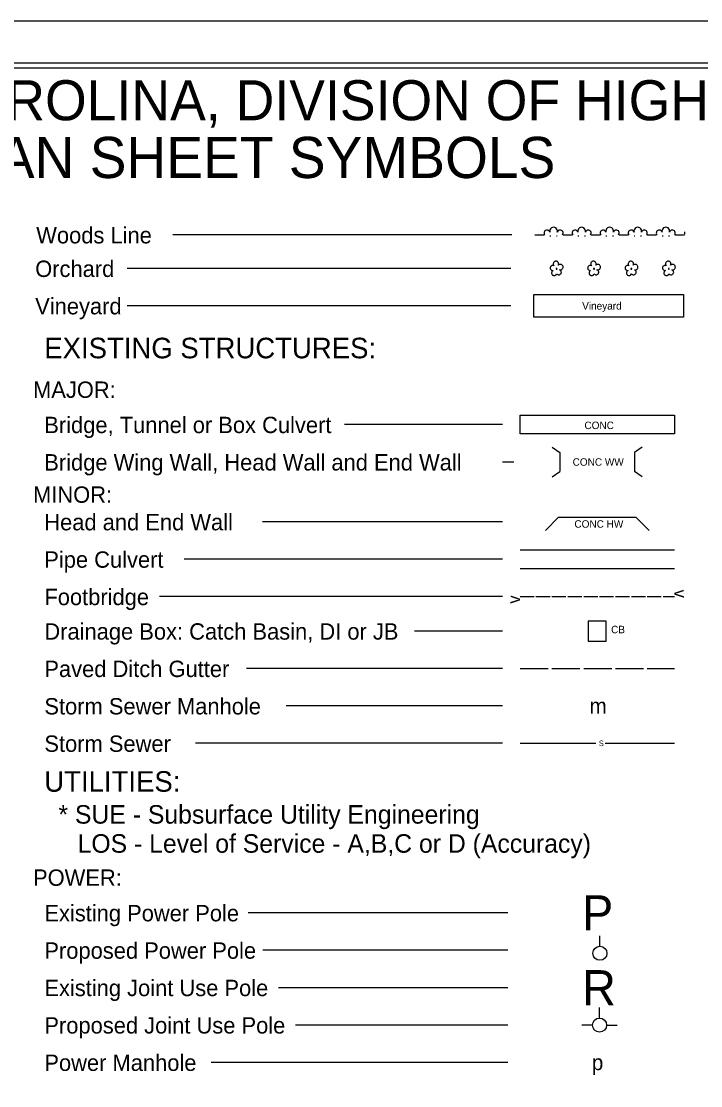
# Model space of a CAD drawing. Extents: x 147589369 to 147592737, y 91898723 to 91900923.
# Drawn here: x 147591216 to 147591942, y 91899785 to 91900923 of the extents above; entities that cross this region are included whole.
import ezdxf

# ---------------------------------------------------------------- set-up
doc = ezdxf.new("R2010")
doc.units = 0
for name, color, linetype in [('Sheet Cutting Line CELL', 7, 'Continuous'), ('Sheet Plot Border Inside CELL', 7, 'Continuous'), ('Sheet Plot Border Outside CELL', 7, 'Continuous'), ('Sheet Symbology CELL', 7, 'Continuous')]:
    doc.layers.add(name, color=color, linetype=linetype)

msp = doc.modelspace()

# ---------------------------------------------------------------- linework, layer by layer
at = {"layer": 'Sheet Cutting Line CELL'}
msp.add_line((147592737.3, 91900923.1), (147589369.3, 91900923.1), dxfattribs=at)
at = {"layer": 'Sheet Plot Border Inside CELL'}
msp.add_lwpolyline([(147589395.3, 91898768), (147592728.3, 91898768), (147592728.3, 91900878.2), (147589395.3, 91900878.2)], close=True, dxfattribs=at)
at = {"layer": 'Sheet Plot Border Outside CELL'}
msp.add_lwpolyline([(147589369.3, 91898723.1), (147592737.3, 91898723.1), (147592737.3, 91900923.1), (147589369.3, 91900923.1)], close=True, dxfattribs=at)
at = {"layer": 'Sheet Symbology CELL'}
for p, q in [((147591739.8, 91900694.5), (147591377.6, 91900694.5)), ((147591764.6, 91900694.5), (147591774.6, 91900694.5)), ((147591780.5, 91900693.5), (147591781.5, 91900693.5)), ((147591787.5, 91900693.5), (147591788.5, 91900693.5)), ((147591794.6, 91900694.5), (147591804.6, 91900694.5)), ((147591810.5, 91900693.5), (147591811.5, 91900693.5)), ((147591817.5, 91900693.5), (147591818.5, 91900693.5)), ((147591824.6, 91900694.5), (147591834.6, 91900694.5)), ((147591840.5, 91900693.5), (147591841.5, 91900693.5)), ((147591847.5, 91900693.5), (147591848.5, 91900693.5)), ((147591854.6, 91900694.5), (147591864.6, 91900694.5)), ((147591870.5, 91900693.5), (147591871.5, 91900693.5)), ((147591877.5, 91900693.5), (147591878.5, 91900693.5)), ((147591884.6, 91900694.5), (147591894.6, 91900694.5)), ((147591900.5, 91900693.5), (147591901.5, 91900693.5)), ((147591907.5, 91900693.5), (147591908.5, 91900693.5)), ((147591914.6, 91900694.5), (147591924.6, 91900694.5)), ((147591738.7, 91900658.7), (147591328.8, 91900658.7)), ((147591738.7, 91900618.7), (147591328.8, 91900618.7)), ((147591730.1, 91900491.7), (147591561.2, 91900491.7)), ((147591783, 91900467.4), (147591791.2, 91900461.7)), ((147591879.4, 91900467.4), (147591871.2, 91900461.7)), ((147591730.1, 91900451.7), (147591742, 91900451.7)), ((147591791.2, 91900461.7), (147591791.2, 91900441.7)), ((147591871.2, 91900461.7), (147591871.2, 91900441.7)), ((147591783, 91900435.9), (147591791.2, 91900441.7)), ((147591879.4, 91900435.9), (147591871.2, 91900441.7)), ((147591730.1, 91900387.7), (147591473.5, 91900387.7)), ((147591775.8, 91900378.5), (147591789.9, 91900392.7)), ((147591789.9, 91900392.7), (147591872.4, 91900392.7)), ((147591872.4, 91900392.7), (147591886.6, 91900378.5)), ((147591748.7, 91900357.7), (147591913.7, 91900357.7)), ((147591730.1, 91900347.7), (147591389.7, 91900347.7)), ((147591748.7, 91900337.7), (147591913.7, 91900337.7)), ((147591730.1, 91900307.7), (147591363.1, 91900307.7)), ((147591748.7, 91900307.7), (147591763.7, 91900307.7)), ((147591765.7, 91900307.7), (147591780.7, 91900307.7)), ((147591782.7, 91900307.7), (147591797.7, 91900307.7)), ((147591799.7, 91900307.7), (147591814.7, 91900307.7)), ((147591816.7, 91900307.7), (147591831.7, 91900307.7)), ((147591833.7, 91900307.7), (147591848.7, 91900307.7)), ((147591850.7, 91900307.7), (147591865.7, 91900307.7)), ((147591867.7, 91900307.7), (147591882.7, 91900307.7)), ((147591884.7, 91900307.7), (147591899.7, 91900307.7)), ((147591901.7, 91900307.7), (147591913.7, 91900307.7)), ((147591730.1, 91900270.8), (147591635.7, 91900270.8)), ((147591730.1, 91900230.8), (147591456.2, 91900230.8)), ((147591748.7, 91900230.8), (147591778.7, 91900230.8)), ((147591782.7, 91900230.8), (147591812.7, 91900230.8)), ((147591816.7, 91900230.8), (147591846.7, 91900230.8)), ((147591850.7, 91900230.8), (147591880.7, 91900230.8)), ((147591884.7, 91900230.8), (147591913.7, 91900230.8)), ((147591730.1, 91900190.8), (147591498.7, 91900190.8)), ((147591730.1, 91900150.8), (147591401.7, 91900150.8)), ((147591748.7, 91900150.8), (147591829.7, 91900150.8)), ((147591839.7, 91900150.8), (147591913.7, 91900150.8)), ((147591735.6, 91899969.4), (147591458.2, 91899969.4)), ((147591834.1, 91899933.7), (147591834.1, 91899944.9)), ((147591735.6, 91899929.4), (147591473.8, 91899929.4)), ((147591735.6, 91899889.4), (147591490.6, 91899889.4)), ((147591833.7, 91899857), (147591833.7, 91899868.2)), ((147591735.6, 91899849.4), (147591508.6, 91899849.4)), ((147591826.2, 91899849.5), (147591814.9, 91899849.5)), ((147591841.2, 91899849.5), (147591852.4, 91899849.5)), ((147591735.6, 91899809.4), (147591418.6, 91899809.4))]:
    msp.add_line(p, q, dxfattribs=at)
for points in [[(147592703.3, 91900873.1), (147589703.3, 91900873.1), (147589703.3, 91898775.1), (147592703.3, 91898775.1)], [(147591821.5, 91900260.2), (147591840.8, 91900260.2), (147591840.8, 91900281.5), (147591821.5, 91900281.5)]]:
    msp.add_lwpolyline(points, close=True, dxfattribs=at)
for points in [[(147591789.6, 91900662.2), (147591789.9, 91900662.8), (147591790, 91900663.4), (147591789.9, 91900664), (147591789.8, 91900664.6), (147591789.5, 91900665.1), (147591789.2, 91900665.6), (147591788.7, 91900666), (147591788.2, 91900666.3), (147591787.5, 91900666.5), (147591787, 91900666.5), (147591786.4, 91900666.4), (147591785.8, 91900666.2), (147591785.3, 91900665.9), (147591784.8, 91900665.5), (147591784.5, 91900664.9), (147591784.3, 91900664.4), (147591784.2, 91900663.8), (147591784.2, 91900663.2), (147591784.3, 91900662.6), (147591784.6, 91900662.1), (147591785, 91900661.5), (147591784.5, 91900661.8), (147591783.9, 91900661.9), (147591783.3, 91900661.9), (147591782.8, 91900661.7), (147591782.3, 91900661.5), (147591781.8, 91900661.1), (147591781.4, 91900660.7), (147591781.1, 91900660.2), (147591781, 91900659.7), (147591780.9, 91900659), (147591781, 91900658.5), (147591781.2, 91900658), (147591781.6, 91900657.5), (147591781.9, 91900657.1), (147591782.4, 91900656.8), (147591783, 91900656.5), (147591783.5, 91900656.4), (147591784.1, 91900656.4), (147591783.6, 91900656.2), (147591783.1, 91900655.8), (147591782.8, 91900655.4), (147591782.6, 91900654.8), (147591782.4, 91900654.2), (147591782.4, 91900653.7), (147591782.5, 91900653.1), (147591782.8, 91900652.6), (147591783.1, 91900652.1), (147591783.5, 91900651.7), (147591784, 91900651.4), (147591784.5, 91900651.2), (147591785.1, 91900651.2), (147591785.7, 91900651.2), (147591786.2, 91900651.3), (147591786.7, 91900651.7), (147591787.2, 91900652), (147591787.7, 91900652.9)], [(147591787.9, 91900658.7), (147591787.6, 91900658.7), (147591787.4, 91900658.6), (147591787.2, 91900658.5), (147591787.2, 91900658.2), (147591787.2, 91900658), (147591787.4, 91900657.8), (147591787.7, 91900657.8), (147591787.9, 91900657.8), (147591788.1, 91900658), (147591788.2, 91900658.3), (147591788.1, 91900658.5), (147591787.9, 91900658.7)], [(147591787.7, 91900652.9), (147591788.9, 91900652.2), (147591789.5, 91900652), (147591790.1, 91900651.9), (147591790.7, 91900652), (147591791.2, 91900652.2), (147591791.7, 91900652.5), (147591792.2, 91900652.9), (147591792.5, 91900653.4), (147591792.7, 91900653.9), (147591792.9, 91900654.5), (147591792.8, 91900655.1), (147591792.7, 91900655.7), (147591792.3, 91900656.3), (147591792, 91900656.7), (147591791.5, 91900657), (147591790.9, 91900657.3), (147591791.5, 91900657.2), (147591792.2, 91900657.2), (147591792.7, 91900657.4), (147591793.3, 91900657.7), (147591793.8, 91900658), (147591794.2, 91900658.5), (147591794.5, 91900659.1), (147591794.6, 91900659.7), (147591794.7, 91900660.3), (147591794.6, 91900660.9), (147591794.4, 91900661.5), (147591794, 91900662), (147591793.5, 91900662.5), (147591793, 91900662.8), (147591792.4, 91900663), (147591791.8, 91900663.1), (147591791.2, 91900663.1), (147591790.6, 91900662.9), (147591790.1, 91900662.6), (147591789.6, 91900662.2)], [(147591829.6, 91900662.2), (147591829.9, 91900662.8), (147591830, 91900663.4), (147591829.9, 91900664), (147591829.8, 91900664.6), (147591829.5, 91900665.1), (147591829.2, 91900665.6), (147591828.7, 91900666), (147591828.2, 91900666.3), (147591827.5, 91900666.5), (147591827, 91900666.5), (147591826.4, 91900666.4), (147591825.8, 91900666.2), (147591825.3, 91900665.9), (147591824.8, 91900665.5), (147591824.5, 91900664.9), (147591824.3, 91900664.4), (147591824.2, 91900663.8), (147591824.2, 91900663.2), (147591824.3, 91900662.6), (147591824.6, 91900662.1), (147591825, 91900661.5), (147591824.5, 91900661.8), (147591823.9, 91900661.9), (147591823.3, 91900661.9), (147591822.8, 91900661.7), (147591822.3, 91900661.5), (147591821.8, 91900661.1), (147591821.4, 91900660.7), (147591821.1, 91900660.2), (147591821, 91900659.7), (147591820.9, 91900659), (147591821, 91900658.5), (147591821.2, 91900658), (147591821.6, 91900657.5), (147591821.9, 91900657.1), (147591822.4, 91900656.8), (147591823, 91900656.5), (147591823.5, 91900656.4), (147591824.1, 91900656.4), (147591823.6, 91900656.2), (147591823.1, 91900655.8), (147591822.8, 91900655.4), (147591822.6, 91900654.8), (147591822.4, 91900654.2), (147591822.4, 91900653.7), (147591822.5, 91900653.1), (147591822.8, 91900652.6), (147591823.1, 91900652.1), (147591823.5, 91900651.7), (147591824, 91900651.4), (147591824.5, 91900651.2), (147591825.1, 91900651.2), (147591825.7, 91900651.2), (147591826.2, 91900651.3), (147591826.7, 91900651.7), (147591827.2, 91900652), (147591827.7, 91900652.9)], [(147591827.9, 91900658.7), (147591827.6, 91900658.7), (147591827.4, 91900658.6), (147591827.2, 91900658.5), (147591827.2, 91900658.2), (147591827.2, 91900658), (147591827.4, 91900657.8), (147591827.7, 91900657.8), (147591827.9, 91900657.8), (147591828.1, 91900658), (147591828.2, 91900658.3), (147591828.1, 91900658.5), (147591827.9, 91900658.7)], [(147591827.7, 91900652.9), (147591828.9, 91900652.2), (147591829.5, 91900652), (147591830.1, 91900651.9), (147591830.7, 91900652), (147591831.2, 91900652.2), (147591831.7, 91900652.5), (147591832.2, 91900652.9), (147591832.5, 91900653.4), (147591832.7, 91900653.9), (147591832.9, 91900654.5), (147591832.8, 91900655.1), (147591832.7, 91900655.7), (147591832.3, 91900656.3), (147591832, 91900656.7), (147591831.5, 91900657), (147591830.9, 91900657.3), (147591831.5, 91900657.2), (147591832.2, 91900657.2), (147591832.7, 91900657.4), (147591833.3, 91900657.7), (147591833.8, 91900658), (147591834.2, 91900658.5), (147591834.5, 91900659.1), (147591834.6, 91900659.7), (147591834.7, 91900660.3), (147591834.6, 91900660.9), (147591834.4, 91900661.5), (147591834, 91900662), (147591833.5, 91900662.5), (147591833, 91900662.8), (147591832.4, 91900663), (147591831.8, 91900663.1), (147591831.2, 91900663.1), (147591830.6, 91900662.9), (147591830.1, 91900662.6), (147591829.6, 91900662.2)], [(147591869.6, 91900662.2), (147591869.9, 91900662.8), (147591870, 91900663.4), (147591869.9, 91900664), (147591869.8, 91900664.6), (147591869.5, 91900665.1), (147591869.2, 91900665.6), (147591868.7, 91900666), (147591868.2, 91900666.3), (147591867.5, 91900666.5), (147591867, 91900666.5), (147591866.4, 91900666.4), (147591865.8, 91900666.2), (147591865.3, 91900665.9), (147591864.8, 91900665.5), (147591864.5, 91900664.9), (147591864.3, 91900664.4), (147591864.2, 91900663.8), (147591864.2, 91900663.2), (147591864.3, 91900662.6), (147591864.6, 91900662.1), (147591865, 91900661.5), (147591864.5, 91900661.8), (147591863.9, 91900661.9), (147591863.3, 91900661.9), (147591862.8, 91900661.7), (147591862.3, 91900661.5), (147591861.8, 91900661.1), (147591861.4, 91900660.7), (147591861.1, 91900660.2), (147591861, 91900659.7), (147591860.9, 91900659), (147591861, 91900658.5), (147591861.2, 91900658), (147591861.6, 91900657.5), (147591861.9, 91900657.1), (147591862.4, 91900656.8), (147591863, 91900656.5), (147591863.5, 91900656.4), (147591864.1, 91900656.4), (147591863.6, 91900656.2), (147591863.1, 91900655.8), (147591862.8, 91900655.4), (147591862.6, 91900654.8), (147591862.4, 91900654.2), (147591862.4, 91900653.7), (147591862.5, 91900653.1), (147591862.8, 91900652.6), (147591863.1, 91900652.1), (147591863.5, 91900651.7), (147591864, 91900651.4), (147591864.5, 91900651.2), (147591865.1, 91900651.2), (147591865.7, 91900651.2), (147591866.2, 91900651.3), (147591866.7, 91900651.7), (147591867.2, 91900652), (147591867.7, 91900652.9)], [(147591867.9, 91900658.7), (147591867.6, 91900658.7), (147591867.4, 91900658.6), (147591867.2, 91900658.5), (147591867.2, 91900658.2), (147591867.2, 91900658), (147591867.4, 91900657.8), (147591867.7, 91900657.8), (147591867.9, 91900657.8), (147591868.1, 91900658), (147591868.2, 91900658.3), (147591868.1, 91900658.5), (147591867.9, 91900658.7)], [(147591867.7, 91900652.9), (147591868.9, 91900652.2), (147591869.5, 91900652), (147591870.1, 91900651.9), (147591870.7, 91900652), (147591871.2, 91900652.2), (147591871.7, 91900652.5), (147591872.2, 91900652.9), (147591872.5, 91900653.4), (147591872.7, 91900653.9), (147591872.9, 91900654.5), (147591872.8, 91900655.1), (147591872.7, 91900655.7), (147591872.3, 91900656.3), (147591872, 91900656.7), (147591871.5, 91900657), (147591870.9, 91900657.3), (147591871.5, 91900657.2), (147591872.2, 91900657.2), (147591872.7, 91900657.4), (147591873.3, 91900657.7), (147591873.8, 91900658), (147591874.2, 91900658.5), (147591874.5, 91900659.1), (147591874.6, 91900659.7), (147591874.7, 91900660.3), (147591874.6, 91900660.9), (147591874.4, 91900661.5), (147591874, 91900662), (147591873.5, 91900662.5), (147591873, 91900662.8), (147591872.4, 91900663), (147591871.8, 91900663.1), (147591871.2, 91900663.1), (147591870.6, 91900662.9), (147591870.1, 91900662.6), (147591869.6, 91900662.2)], [(147591909.6, 91900662.2), (147591909.9, 91900662.8), (147591910, 91900663.4), (147591909.9, 91900664), (147591909.8, 91900664.6), (147591909.5, 91900665.1), (147591909.2, 91900665.6), (147591908.7, 91900666), (147591908.2, 91900666.3), (147591907.5, 91900666.5), (147591907, 91900666.5), (147591906.4, 91900666.4), (147591905.8, 91900666.2), (147591905.3, 91900665.9), (147591904.8, 91900665.5), (147591904.5, 91900664.9), (147591904.3, 91900664.4), (147591904.2, 91900663.8), (147591904.2, 91900663.2), (147591904.3, 91900662.6), (147591904.6, 91900662.1), (147591905, 91900661.5), (147591904.5, 91900661.8), (147591903.9, 91900661.9), (147591903.3, 91900661.9), (147591902.8, 91900661.7), (147591902.3, 91900661.5), (147591901.8, 91900661.1), (147591901.4, 91900660.7), (147591901.1, 91900660.2), (147591901, 91900659.7), (147591900.9, 91900659), (147591901, 91900658.5), (147591901.2, 91900658), (147591901.6, 91900657.5), (147591901.9, 91900657.1), (147591902.4, 91900656.8), (147591903, 91900656.5), (147591903.5, 91900656.4), (147591904.1, 91900656.4), (147591903.6, 91900656.2), (147591903.1, 91900655.8), (147591902.8, 91900655.4), (147591902.6, 91900654.8), (147591902.4, 91900654.2), (147591902.4, 91900653.7), (147591902.5, 91900653.1), (147591902.8, 91900652.6), (147591903.1, 91900652.1), (147591903.5, 91900651.7), (147591904, 91900651.4), (147591904.5, 91900651.2), (147591905.1, 91900651.2), (147591905.7, 91900651.2), (147591906.2, 91900651.3), (147591906.7, 91900651.7), (147591907.2, 91900652), (147591907.7, 91900652.9)], [(147591907.9, 91900658.7), (147591907.6, 91900658.7), (147591907.4, 91900658.6), (147591907.2, 91900658.5), (147591907.2, 91900658.2), (147591907.2, 91900658), (147591907.4, 91900657.8), (147591907.7, 91900657.8), (147591907.9, 91900657.8), (147591908.1, 91900658), (147591908.2, 91900658.3), (147591908.1, 91900658.5), (147591907.9, 91900658.7)], [(147591907.7, 91900652.9), (147591908.9, 91900652.2), (147591909.5, 91900652), (147591910.1, 91900651.9), (147591910.7, 91900652), (147591911.2, 91900652.2), (147591911.7, 91900652.5), (147591912.2, 91900652.9), (147591912.5, 91900653.4), (147591912.7, 91900653.9), (147591912.9, 91900654.5), (147591912.8, 91900655.1), (147591912.7, 91900655.7), (147591912.3, 91900656.3), (147591912, 91900656.7), (147591911.5, 91900657), (147591910.9, 91900657.3), (147591911.5, 91900657.2), (147591912.2, 91900657.2), (147591912.7, 91900657.4), (147591913.3, 91900657.7), (147591913.8, 91900658), (147591914.2, 91900658.5), (147591914.5, 91900659.1), (147591914.6, 91900659.7), (147591914.7, 91900660.3), (147591914.6, 91900660.9), (147591914.4, 91900661.5), (147591914, 91900662), (147591913.5, 91900662.5), (147591913, 91900662.8), (147591912.4, 91900663), (147591911.8, 91900663.1), (147591911.2, 91900663.1), (147591910.6, 91900662.9), (147591910.1, 91900662.6), (147591909.6, 91900662.2)], [(147591763.5, 91900630.7), (147591923.5, 91900630.7), (147591923.5, 91900606.7), (147591763.5, 91900606.7), (147591763.5, 91900630.7)], [(147591748.7, 91900501.7), (147591913.7, 91900501.7), (147591913.7, 91900481.7), (147591748.7, 91900481.7), (147591748.7, 91900501.7)]]:
    msp.add_lwpolyline(points, dxfattribs=at)
for centre in [(147591834.1, 91899926.2), (147591833.7, 91899849.4)]:
    msp.add_circle(centre, 7.5, dxfattribs=at)
for centre, radius, start, end in [((147591784.5, 91900698.6), 4.12, 345.9638, 194.0362), ((147591814.5, 91900698.6), 4.12, 345.9638, 194.0362), ((147591844.5, 91900698.6), 4.12, 345.9638, 194.0362), ((147591874.5, 91900698.6), 4.12, 345.9638, 194.0362), ((147591904.5, 91900698.6), 4.12, 345.9638, 194.0362), ((147591777.5, 91900696.6), 3.16, 18.435, 219.2315), ((147591791.5, 91900696.6), 3.16, 320.7685, 161.5651), ((147591807.5, 91900696.6), 3.16, 18.435, 219.2315), ((147591821.5, 91900696.6), 3.16, 320.7685, 161.5651), ((147591837.5, 91900696.6), 3.16, 18.435, 219.2315), ((147591851.5, 91900696.6), 3.16, 320.7685, 161.5651), ((147591867.5, 91900696.6), 3.16, 18.435, 219.2315), ((147591881.5, 91900696.6), 3.16, 320.7685, 161.5651), ((147591897.5, 91900696.6), 3.16, 18.435, 219.2315), ((147591911.5, 91900696.6), 3.16, 320.7685, 161.5651), ((147591927.5, 91900696.6), 3.16, 156.251, 203.749)]:
    msp.add_arc(centre, radius, start, end, dxfattribs=at)

# ---------------------------------------------------------------- texts
for s, height, p in [('STATE OF NORTH CAROLINA, DIVISION OF HIGHWAYS', 42.838, (147590604.4, 91900817.2)), ('CONVENTIONAL  PLAN SHEET SYMBOLS', 44.065, (147590620.7, 91900755.4)), ('Woods Line', 17.5, (147591231.5, 91900685.5)), ('Orchard', 17.5, (147591230.4, 91900649.6)), ('Vineyard', 17.5, (147591230.4, 91900609.6)), ('EXISTING STRUCTURES:', 22, (147591240.1, 91900562.6)), ('MAJOR:', 17.5, (147591228.1, 91900520.3)), ('Bridge, Tunnel or Box Culvert', 17.5, (147591240.1, 91900482.6)), ('CONC', 8, (147591817.5, 91900486.9)), ('Bridge Wing Wall, Head Wall and End Wall', 17.5, (147591240.1, 91900442.6)), ('MINOR:', 17.5, (147591228.1, 91900408.1)), ('Head and End Wall', 17.5, (147591240.1, 91900378.6)), ('Pipe Culvert', 17.5, (147591240.1, 91900338.6)), ('Footbridge', 17.5, (147591240.2, 91900298.6)), ('Drainage Box: Catch Basin, DI or JB', 17.5, (147591240.2, 91900261.7)), ('Paved Ditch Gutter', 17.5, (147591240.2, 91900221.7)), ('Storm Sewer Manhole', 17.5, (147591240.2, 91900181.7)), ('m', 16.5, (147591822.9, 91900182.6)), ('Storm Sewer', 17.5, (147591240.2, 91900141.7)), ('S', 6, (147591832.9, 91900147.8)), ('UTILITIES:', 22, (147591240.1, 91900099)), ('POWER:', 17.5, (147591228.1, 91899998.4)), ('P', 37.5, (147591814.9, 91899950.7)), ('Existing Power Pole', 17.5, (147591240.2, 91899960.4)), ('Proposed Power Pole', 17.5, (147591240.2, 91899920.4)), ('R', 37.5, (147591814.9, 91899870.7)), ('Existing Joint Use Pole', 17.5, (147591240.2, 91899880.4)), ('Proposed Joint Use Pole', 17.5, (147591240.2, 91899840.4)), ('Power Manhole', 17.5, (147591240.2, 91899800.4)), ('p', 16.5, (147591825.4, 91899801.2))]:
    msp.add_text(s, height=height, dxfattribs=at).set_placement(p)
for s, height, rotation, p in [('Vineyard', 8, 0, (147591815.1, 91900614.7)), ('CONC WW', 8, 0, (147591804.9, 91900447.7)), ('CONC HW', 8, 360, (147591806.8, 91900381.4)), ('v', 13.2, 270.2409, (147591913.6, 91900315.2)), ('v', 13.2, 89.7591, (147591748.6, 91900300.2)), ('CB', 8, 360, (147591846, 91900268.5)), ('* SUE - Subsurface Utility Engineering', 19.8, 360, (147591255.2, 91900064.9)), ('LOS - Level of Service - A,B,C or D (Accuracy) ', 19.8, 360, (147591275.7, 91900033.8))]:
    msp.add_text(s, height=height, rotation=rotation, dxfattribs=at).set_placement(p)

doc.saveas('drawing.dxf')
